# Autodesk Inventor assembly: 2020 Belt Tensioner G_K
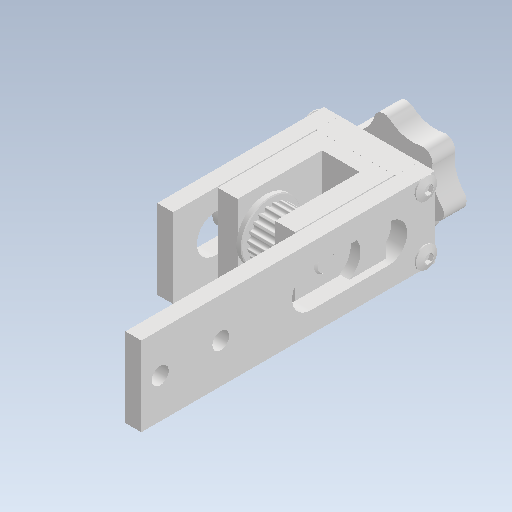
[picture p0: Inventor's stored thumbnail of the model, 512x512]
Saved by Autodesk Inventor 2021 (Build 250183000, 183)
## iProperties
Created: 2023-10
Part Number: 2020 Belt Tensioner G_K
Document SubType Name: Assembly
Designer: hp
Author: hp
Revision Number: ANY
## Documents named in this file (9)
- C:\Users\hp\Downloads\low-cost-linear-guide-for-automation-training-with-nema-17-1.snapshot.1\2020 Belt Tensioner G_K.iam
- C:\Users\hp\Downloads\low-cost-linear-guide-for-automation-training-with-nema-17-1.snapshot.1\2020 Tensioner Pulley Cradle.ipt
- C:\Users\hp\Downloads\low-cost-linear-guide-for-automation-training-with-nema-17-1.snapshot.1\2020 Tensioner Rear.ipt
- C:\Users\hp\Downloads\low-cost-linear-guide-for-automation-training-with-nema-17-1.snapshot.1\2020 Tensioner Short side.ipt
- C:\Users\hp\Downloads\low-cost-linear-guide-for-automation-training-with-nema-17-1.snapshot.1\2020 Tensioner Long side.ipt
- C:\Users\hp\Downloads\low-cost-linear-guide-for-automation-training-with-nema-17-1.snapshot.1\2020 Tensioner Adjusting Screw.ipt
- C:\Users\hp\Downloads\low-cost-linear-guide-for-automation-training-with-nema-17-1.snapshot.1\M5 Cap head Screw.ipt
- C:\Users\hp\Downloads\low-cost-linear-guide-for-automation-training-with-nema-17-1.snapshot.1\GT2_Idler_20T_6mm.step.iam
- C:\Users\hp\Downloads\low-cost-linear-guide-for-automation-training-with-nema-17-1.snapshot.1\M3x10mm bolt.ipt
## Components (11 placed, 11 different names)
1. 2020 Tensioner Pulley Cradle_1
2. 2020 Tensioner Rear_2
3. 2020 Tensioner Short side_3
4. 2020 Tensioner Long side_4
5. 2020 Tensioner Adjusting Screw_5
6. M5 Cap head Screw_6
7. GT2_Idler_20T_6mm.step_7 [sub-assembly]
8. M3x10mm bolt_8
9. M3x10mm bolt_9
10. M3x10mm bolt_10
11. M3x10mm bolt_11
